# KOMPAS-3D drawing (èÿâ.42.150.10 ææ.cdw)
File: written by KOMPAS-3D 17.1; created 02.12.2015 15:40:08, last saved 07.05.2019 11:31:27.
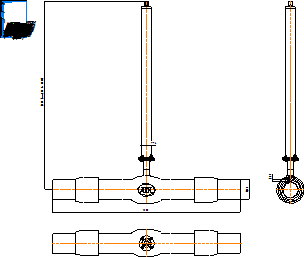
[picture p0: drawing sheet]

Sheet 1: A4, portrait

Title block, sheet 1: name: КШГ.42.150.10 СС; material: Внимание! Данный продукт является объектом авторского права ООО «Торговый Дом АДЛ». / Запрещается изменение, копирование, распространение / (в том числе путем копирования на другие сайты и ресурсы в Интернете) / или любое иное использование информации и объектов без предварительного / согласия правообладателя (ООО «Торговый Дом АДЛ»).; sheets: 1; organisation: ООО "Торговый дом АДЛ"; sheet format: A4; stored path: C:\Users\kka\KOMPAS_Work\Модели кранов для исследований\DN50\С удлинением\КШГ.32.050.40 СС ГЧ _ Шаровой кран БИВАЛ Ду50 Ру4 МПа редуцированный под приварку, с удлинением штока H=1100.cdw; drawn by: Климкович К.А.; drawn by, date: 07.12.16

Views: Вид 1, Проекционный вид 2
Referenced files in C:\Users\kka\KOMPAS_Work\Модели кранов для исследований\DN80\С удлинением\: КШТ.22.080.25 СС.a3d
Referenced files in C:\Users\kka\KOMPAS_Work\Модели кранов для исследований\DN150\С удлинением\: КШТ.22.150.25 СС.a3d, КШГ.35.125.25 СС Lстр600.a3d, КШГ.35.125.25 СС Lстр600.a3d!Деталь (локальная).m3d
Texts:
  Klimkovich
  ADL
  (от 480 до 5000)
Dimensions and other numbers on the sheet: 76; 160; 1500; 14,6; 1:1; 1; 07.12.16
